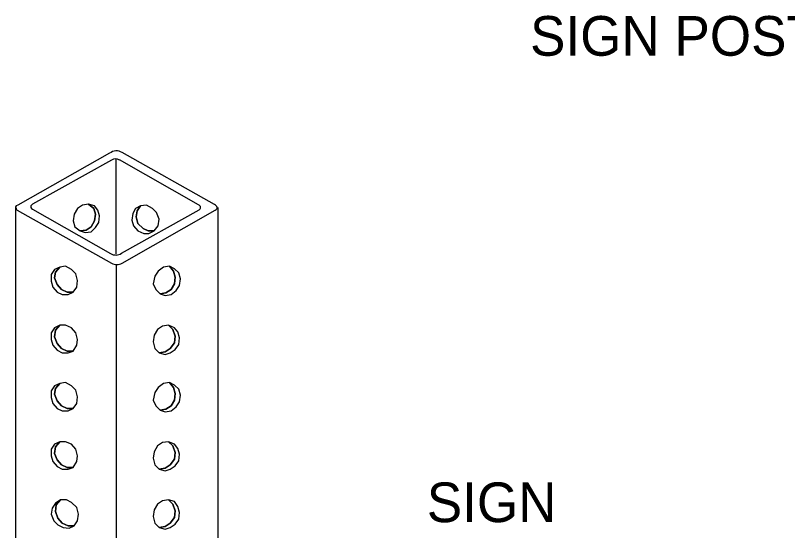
# Model space of a CAD drawing. Extents: x 99862 to 103680, y 99470 to 102076.
# Drawn here: x 100406.5 to 100717.9, y 100290.3 to 100498 of the extents above; entities that cross this region are included whole.
import ezdxf

# ---------------------------------------------------------------- set-up
doc = ezdxf.new("R2010")
doc.units = 0
doc.layers.add('Level 2', color=7, linetype='Continuous')
doc.layers.add('Level 20', color=7, linetype='Continuous')

msp = doc.modelspace()

# ---------------------------------------------------------------- linework, layer by layer
at = {"layer": 'Level 2'}
for p, q in [((100444.49, 100442.41), (100407.52, 100421.53)), ((100486.78, 100421.72), (100449.53, 100442.7)), ((100445.25, 100439.63), (100413.35, 100421.87)), ((100446.97, 100439.97), (100446.97, 100401.75)), ((100480.33, 100421.68), (100448.41, 100439.77)), ((100406.83, 100421.2), (100406.49, 100420.86)), ((100406.49, 100420.86), (100406.49, 100420.53)), ((100406.49, 100420.53), (100406.83, 100420.19)), ((100406.49, 100420.53), (100406.49, 100093.86)), ((100407.52, 100421.53), (100406.83, 100421.2)), ((100413.01, 100421.53), (100412.66, 100421.2)), ((100412.66, 100421.2), (100412.66, 100420.86)), ((100412.66, 100420.86), (100412.66, 100420.53)), ((100412.66, 100420.53), (100413.01, 100420.19)), ((100413.35, 100421.87), (100413.01, 100421.53)), ((100433.59, 100421.53), (100431.53, 100420.19)), ((100435.99, 100421.87), (100433.59, 100421.53)), ((100438.05, 100420.19), (100435.99, 100421.87)), ((100438.39, 100421.2), (100435.99, 100421.87)), ((100435.99, 100421.87), (100438.05, 100420.19)), ((100439.77, 100419.52), (100438.39, 100421.2)), ((100456.92, 100421.2), (100454.86, 100420.19)), ((100456.92, 100421.2), (100455.55, 100419.18)), ((100455.55, 100419.18), (100456.92, 100421.2)), ((100459.32, 100421.53), (100456.92, 100421.2)), ((100461.72, 100420.19), (100459.32, 100421.53)), ((100488.14, 100420.6), (100488.14, 100093.86)), ((100406.83, 100420.19), (100406.83, 100419.86)), ((100406.83, 100419.86), (100407.18, 100419.52)), ((100407.18, 100419.52), (100445.25, 100398.07)), ((100413.01, 100420.19), (100413.35, 100419.86)), ((100413.35, 100419.86), (100444.88, 100401.97)), ((100430.16, 100417.84), (100429.82, 100415.16)), ((100431.53, 100420.19), (100430.16, 100417.84)), ((100438.74, 100417.84), (100438.05, 100420.19)), ((100438.05, 100420.19), (100438.74, 100417.84)), ((100438.39, 100415.16), (100438.74, 100417.84)), ((100438.74, 100417.84), (100438.39, 100415.16)), ((100440.45, 100417.17), (100439.77, 100419.52)), ((100449.31, 100402.1), (100480.55, 100419.64)), ((100449.57, 100398.18), (100487.11, 100419.52)), ((100453.83, 100418.18), (100453.49, 100415.5)), ((100454.86, 100420.19), (100453.83, 100418.18)), ((100455.55, 100419.18), (100455.2, 100416.84)), ((100455.2, 100416.84), (100455.55, 100419.18)), ((100463.44, 100418.51), (100461.72, 100420.19)), ((100464.47, 100415.83), (100463.44, 100418.51)), ((100487.11, 100419.52), (100487.11, 100419.52)), ((100429.82, 100415.16), (100430.5, 100412.82)), ((100437.02, 100412.82), (100438.39, 100415.16)), ((100438.39, 100415.16), (100437.02, 100412.82)), ((100438.74, 100412.48), (100440.11, 100414.49)), ((100440.11, 100414.49), (100440.45, 100417.17)), ((100453.49, 100415.5), (100454.17, 100413.15)), ((100455.2, 100416.84), (100455.89, 100414.16)), ((100455.89, 100414.16), (100455.2, 100416.84)), ((100464.12, 100413.15), (100464.47, 100415.83)), ((100430.5, 100412.82), (100432.56, 100411.14)), ((100432.56, 100411.14), (100434.96, 100411.47)), ((100434.96, 100411.47), (100432.56, 100411.14)), ((100434.96, 100411.47), (100437.02, 100412.82)), ((100437.02, 100412.82), (100434.96, 100411.47)), ((100437.02, 100410.8), (100438.74, 100412.48)), ((100454.17, 100413.15), (100455.89, 100411.14)), ((100455.89, 100414.16), (100457.95, 100412.15)), ((100457.95, 100412.15), (100455.89, 100414.16)), ((100457.95, 100412.15), (100460.01, 100411.14)), ((100460.01, 100411.14), (100457.95, 100412.15)), ((100462.41, 100411.14), (100464.12, 100413.15)), ((100432.56, 100411.14), (100434.62, 100410.47)), ((100434.62, 100410.47), (100437.02, 100410.8)), ((100455.89, 100411.14), (100458.29, 100410.13)), ((100458.29, 100410.13), (100460.35, 100410.13)), ((100460.01, 100411.14), (100462.41, 100411.14)), ((100462.41, 100411.14), (100460.01, 100411.14)), ((100460.35, 100410.13), (100462.41, 100411.14)), ((100424.33, 100396.56), (100422.27, 100395.55)), ((100424.33, 100396.56), (100422.61, 100394.55)), ((100422.61, 100394.55), (100424.33, 100396.56)), ((100426.73, 100396.89), (100424.33, 100396.56)), ((100429.13, 100395.55), (100426.73, 100396.89)), ((100447.31, 100071.74), (100447.31, 100397.53)), ((100466.18, 100396.56), (100464.12, 100394.88)), ((100468.58, 100396.89), (100466.18, 100396.56)), ((100470.3, 100394.88), (100468.58, 100396.89)), ((100470.64, 100395.89), (100468.58, 100396.89)), ((100468.58, 100396.89), (100470.3, 100394.88)), ((100472.36, 100394.21), (100470.64, 100395.89)), ((100422.27, 100395.55), (100420.9, 100393.54)), ((100420.9, 100393.54), (100420.9, 100390.86)), ((100422.61, 100394.55), (100422.27, 100392.2)), ((100422.27, 100392.2), (100422.61, 100394.55)), ((100430.85, 100393.88), (100429.13, 100395.55)), ((100431.53, 100391.19), (100430.85, 100393.88)), ((100462.75, 100392.87), (100462.06, 100389.85)), ((100464.12, 100394.88), (100462.75, 100392.87)), ((100470.98, 100392.54), (100470.3, 100394.88)), ((100470.3, 100394.88), (100470.98, 100392.54)), ((100470.64, 100389.85), (100470.98, 100392.54)), ((100470.98, 100392.54), (100470.64, 100389.85)), ((100473.04, 100391.86), (100472.36, 100394.21)), ((100420.9, 100390.86), (100421.58, 100388.51)), ((100422.27, 100392.2), (100423.3, 100389.52)), ((100423.3, 100389.52), (100422.27, 100392.2)), ((100423.3, 100389.52), (100425.01, 100387.51)), ((100425.01, 100387.51), (100423.3, 100389.52)), ((100431.19, 100388.51), (100431.53, 100391.19)), ((100462.06, 100389.85), (100463.09, 100387.51)), ((100469.27, 100387.51), (100470.64, 100389.85)), ((100470.64, 100389.85), (100469.27, 100387.51)), ((100472.7, 100389.18), (100473.04, 100391.86)), ((100421.58, 100388.51), (100423.3, 100386.5)), ((100423.3, 100386.5), (100425.36, 100385.5)), ((100425.01, 100387.51), (100427.42, 100386.5)), ((100427.42, 100386.5), (100425.01, 100387.51)), ((100427.42, 100386.5), (100429.82, 100386.5)), ((100429.82, 100386.5), (100427.42, 100386.5)), ((100427.76, 100385.5), (100429.82, 100386.5)), ((100429.82, 100386.5), (100431.19, 100388.51)), ((100463.09, 100387.51), (100464.81, 100385.83)), ((100467.21, 100386.17), (100469.27, 100387.51)), ((100469.27, 100387.51), (100467.21, 100386.17)), ((100469.27, 100385.5), (100471.33, 100387.17)), ((100471.33, 100387.17), (100472.7, 100389.18)), ((100425.36, 100385.5), (100427.76, 100385.5)), ((100464.81, 100385.83), (100467.21, 100386.17)), ((100467.21, 100386.17), (100464.81, 100385.83)), ((100464.81, 100385.83), (100466.87, 100385.16)), ((100466.87, 100385.16), (100469.27, 100385.5)), ((100422.27, 100372.09), (100420.9, 100370.08)), ((100424.33, 100373.09), (100422.27, 100372.09)), ((100422.61, 100371.08), (100422.27, 100368.4)), ((100422.27, 100368.4), (100422.61, 100371.08)), ((100424.33, 100373.09), (100422.61, 100371.08)), ((100422.61, 100371.08), (100424.33, 100373.09)), ((100426.73, 100373.09), (100424.33, 100373.09)), ((100429.13, 100372.09), (100426.73, 100373.09)), ((100430.85, 100370.08), (100429.13, 100372.09)), ((100463.78, 100371.42), (100462.41, 100369.07)), ((100465.84, 100372.76), (100463.78, 100371.42)), ((100468.24, 100373.09), (100465.84, 100372.76)), ((100469.95, 100371.42), (100468.24, 100373.09)), ((100470.64, 100372.09), (100468.24, 100373.09)), ((100468.24, 100373.09), (100469.95, 100371.42)), ((100470.98, 100368.73), (100469.95, 100371.42)), ((100469.95, 100371.42), (100470.98, 100368.73)), ((100472.01, 100370.41), (100470.64, 100372.09)), ((100420.9, 100370.08), (100420.9, 100367.39)), ((100422.27, 100368.4), (100423.3, 100365.72)), ((100423.3, 100365.72), (100422.27, 100368.4)), ((100431.53, 100367.39), (100430.85, 100370.08)), ((100462.41, 100369.07), (100462.06, 100366.39)), ((100470.64, 100366.05), (100470.98, 100368.73)), ((100470.98, 100368.73), (100470.64, 100366.05)), ((100472.7, 100368.06), (100472.01, 100370.41)), ((100472.36, 100365.38), (100472.7, 100368.06)), ((100420.9, 100367.39), (100421.58, 100365.05)), ((100421.58, 100365.05), (100423.3, 100363.04)), ((100423.3, 100365.72), (100425.01, 100363.71)), ((100425.01, 100363.71), (100423.3, 100365.72)), ((100429.82, 100362.7), (100431.19, 100365.05)), ((100431.19, 100365.05), (100431.53, 100367.39)), ((100462.06, 100366.39), (100462.75, 100363.71)), ((100468.93, 100363.71), (100470.64, 100366.05)), ((100470.64, 100366.05), (100468.93, 100363.71)), ((100470.98, 100363.37), (100472.36, 100365.38)), ((100423.3, 100363.04), (100425.36, 100362.03)), ((100425.01, 100363.71), (100427.42, 100362.7)), ((100427.42, 100362.7), (100425.01, 100363.71)), ((100425.36, 100362.03), (100427.76, 100362.03)), ((100427.42, 100362.7), (100429.82, 100362.7)), ((100429.82, 100362.7), (100427.42, 100362.7)), ((100427.76, 100362.03), (100429.82, 100362.7)), ((100462.75, 100363.71), (100464.47, 100362.03)), ((100464.47, 100362.03), (100466.87, 100362.37)), ((100466.87, 100362.37), (100464.47, 100362.03)), ((100464.47, 100362.03), (100466.87, 100361.36)), ((100466.87, 100362.37), (100468.93, 100363.71)), ((100468.93, 100363.71), (100466.87, 100362.37)), ((100466.87, 100361.36), (100468.93, 100362.03)), ((100468.93, 100362.03), (100470.98, 100363.37)), ((100424.33, 100349.63), (100422.27, 100348.62)), ((100424.33, 100349.63), (100422.61, 100347.62)), ((100422.61, 100347.62), (100424.33, 100349.63)), ((100426.73, 100349.96), (100424.33, 100349.63)), ((100429.13, 100348.62), (100426.73, 100349.96)), ((100466.18, 100349.63), (100464.12, 100347.95)), ((100468.58, 100349.96), (100466.18, 100349.63)), ((100470.3, 100347.95), (100468.58, 100349.96)), ((100470.64, 100348.96), (100468.58, 100349.96)), ((100468.58, 100349.96), (100470.3, 100347.95)), ((100472.36, 100347.28), (100470.64, 100348.96)), ((100422.27, 100348.62), (100420.9, 100346.61)), ((100420.9, 100346.61), (100420.9, 100343.93)), ((100422.61, 100347.62), (100422.27, 100345.27)), ((100422.27, 100345.27), (100422.61, 100347.62)), ((100430.85, 100346.95), (100429.13, 100348.62)), ((100431.53, 100344.26), (100430.85, 100346.95)), ((100462.75, 100345.94), (100462.06, 100342.92)), ((100464.12, 100347.95), (100462.75, 100345.94)), ((100470.98, 100345.61), (100470.3, 100347.95)), ((100470.3, 100347.95), (100470.98, 100345.61)), ((100473.04, 100344.93), (100472.36, 100347.28)), ((100420.9, 100343.93), (100421.58, 100341.58)), ((100422.27, 100345.27), (100423.3, 100342.59)), ((100423.3, 100342.59), (100422.27, 100345.27)), ((100431.19, 100341.58), (100431.53, 100344.26)), ((100462.06, 100342.92), (100463.09, 100340.58)), ((100469.27, 100340.58), (100470.64, 100342.92)), ((100470.64, 100342.92), (100469.27, 100340.58)), ((100470.64, 100342.92), (100470.98, 100345.61)), ((100470.98, 100345.61), (100470.64, 100342.92)), ((100472.7, 100342.25), (100473.04, 100344.93)), ((100421.58, 100341.58), (100423.3, 100339.57)), ((100423.3, 100342.59), (100425.01, 100340.58)), ((100425.01, 100340.58), (100423.3, 100342.59)), ((100423.3, 100339.57), (100425.36, 100338.57)), ((100425.01, 100340.58), (100427.42, 100339.57)), ((100427.42, 100339.57), (100425.01, 100340.58)), ((100427.42, 100339.57), (100429.82, 100339.57)), ((100429.82, 100339.57), (100427.42, 100339.57)), ((100427.76, 100338.57), (100429.82, 100339.57)), ((100429.82, 100339.57), (100431.19, 100341.58)), ((100463.09, 100340.58), (100464.81, 100338.9)), ((100467.21, 100339.24), (100469.27, 100340.58)), ((100469.27, 100340.58), (100467.21, 100339.24)), ((100469.27, 100338.57), (100471.33, 100340.24)), ((100471.33, 100340.24), (100472.7, 100342.25)), ((100425.36, 100338.57), (100427.76, 100338.57)), ((100464.81, 100338.9), (100467.21, 100339.24)), ((100467.21, 100339.24), (100464.81, 100338.9)), ((100464.81, 100338.9), (100466.87, 100338.23)), ((100466.87, 100338.23), (100469.27, 100338.57)), ((100422.27, 100325.16), (100420.9, 100323.15)), ((100424.33, 100326.16), (100422.27, 100325.16)), ((100422.61, 100324.15), (100422.27, 100321.47)), ((100422.27, 100321.47), (100422.61, 100324.15)), ((100424.33, 100326.16), (100422.61, 100324.15)), ((100422.61, 100324.15), (100424.33, 100326.16)), ((100426.73, 100326.16), (100424.33, 100326.16)), ((100429.13, 100325.16), (100426.73, 100326.16)), ((100430.85, 100323.15), (100429.13, 100325.16)), ((100463.78, 100324.49), (100462.41, 100322.14)), ((100465.84, 100325.83), (100463.78, 100324.49)), ((100468.24, 100326.16), (100465.84, 100325.83)), ((100469.95, 100324.49), (100468.24, 100326.16)), ((100470.64, 100325.16), (100468.24, 100326.16)), ((100468.24, 100326.16), (100469.95, 100324.49)), ((100470.98, 100321.8), (100469.95, 100324.49)), ((100469.95, 100324.49), (100470.98, 100321.8)), ((100472.01, 100323.48), (100470.64, 100325.16)), ((100420.9, 100323.15), (100420.9, 100320.46)), ((100422.27, 100321.47), (100423.3, 100318.79)), ((100423.3, 100318.79), (100422.27, 100321.47)), ((100431.53, 100320.46), (100430.85, 100323.15)), ((100462.41, 100322.14), (100462.06, 100319.46)), ((100470.64, 100319.12), (100470.98, 100321.8)), ((100470.98, 100321.8), (100470.64, 100319.12)), ((100472.7, 100321.13), (100472.01, 100323.48)), ((100472.36, 100318.45), (100472.7, 100321.13)), ((100420.9, 100320.46), (100421.58, 100318.12)), ((100421.58, 100318.12), (100423.3, 100316.11)), ((100423.3, 100318.79), (100425.01, 100316.78)), ((100425.01, 100316.78), (100423.3, 100318.79)), ((100429.82, 100315.77), (100431.19, 100318.12)), ((100431.19, 100318.12), (100431.53, 100320.46)), ((100462.06, 100319.46), (100462.75, 100316.78)), ((100468.93, 100316.78), (100470.64, 100319.12)), ((100470.64, 100319.12), (100468.93, 100316.78)), ((100470.98, 100316.44), (100472.36, 100318.45)), ((100423.3, 100316.11), (100425.36, 100315.1)), ((100425.01, 100316.78), (100427.42, 100315.77)), ((100427.42, 100315.77), (100425.01, 100316.78)), ((100425.36, 100315.1), (100427.76, 100315.1)), ((100427.42, 100315.77), (100429.82, 100315.77)), ((100429.82, 100315.77), (100427.42, 100315.77)), ((100427.76, 100315.1), (100429.82, 100315.77)), ((100462.75, 100316.78), (100464.47, 100315.1)), ((100464.47, 100315.1), (100466.87, 100315.44)), ((100466.87, 100315.44), (100464.47, 100315.1)), ((100464.47, 100315.1), (100466.87, 100314.43)), ((100466.87, 100315.44), (100468.93, 100316.78)), ((100468.93, 100316.78), (100466.87, 100315.44)), ((100466.87, 100314.43), (100468.93, 100315.1)), ((100468.93, 100315.1), (100470.98, 100316.44)), ((100424.67, 100302.7), (100422.61, 100301.36)), ((100424.67, 100302.7), (100422.96, 100300.69)), ((100422.96, 100300.69), (100424.67, 100302.7)), ((100427.07, 100302.7), (100424.67, 100302.7)), ((100429.13, 100301.69), (100427.07, 100302.7)), ((100465.84, 100302.36), (100463.78, 100301.02)), ((100468.24, 100302.7), (100465.84, 100302.36)), ((100469.95, 100301.02), (100468.24, 100302.7)), ((100470.64, 100302.03), (100468.24, 100302.7)), ((100468.24, 100302.7), (100469.95, 100301.02)), ((100421.24, 100299.35), (100420.9, 100297)), ((100422.61, 100301.36), (100421.24, 100299.35)), ((100422.96, 100300.69), (100422.61, 100298)), ((100422.61, 100298), (100422.96, 100300.69)), ((100431.19, 100299.68), (100429.13, 100301.69)), ((100431.88, 100297), (100431.19, 100299.68)), ((100463.78, 100301.02), (100462.41, 100298.68)), ((100470.98, 100298.34), (100469.95, 100301.02)), ((100469.95, 100301.02), (100470.98, 100298.34)), ((100472.01, 100300.02), (100470.64, 100302.03)), ((100472.7, 100297.67), (100472.01, 100300.02)), ((100420.9, 100297), (100421.93, 100294.32)), ((100422.61, 100298), (100423.64, 100295.32)), ((100423.64, 100295.32), (100422.61, 100298)), ((100431.53, 100294.32), (100431.88, 100297)), ((100462.41, 100298.68), (100462.06, 100295.99)), ((100462.06, 100295.99), (100462.75, 100293.31)), ((100470.64, 100295.66), (100470.98, 100298.34)), ((100470.98, 100298.34), (100470.64, 100295.66)), ((100472.36, 100294.99), (100472.7, 100297.67)), ((100421.93, 100294.32), (100423.64, 100292.64)), ((100423.64, 100295.32), (100425.36, 100293.31)), ((100425.36, 100293.31), (100423.64, 100295.32)), ((100425.36, 100293.31), (100427.76, 100292.31)), ((100427.76, 100292.31), (100425.36, 100293.31)), ((100430.16, 100292.31), (100431.53, 100294.32)), ((100462.75, 100293.31), (100464.47, 100291.64)), ((100466.87, 100291.97), (100468.93, 100293.31)), ((100468.93, 100293.31), (100466.87, 100291.97)), ((100468.93, 100293.31), (100470.64, 100295.66)), ((100470.64, 100295.66), (100468.93, 100293.31)), ((100468.93, 100291.64), (100470.98, 100292.98)), ((100470.98, 100292.98), (100472.36, 100294.99)), ((100423.64, 100292.64), (100425.7, 100291.64)), ((100425.7, 100291.64), (100428.1, 100291.3)), ((100427.76, 100292.31), (100430.16, 100292.31)), ((100430.16, 100292.31), (100427.76, 100292.31)), ((100428.1, 100291.3), (100430.16, 100292.31)), ((100464.47, 100291.64), (100466.87, 100291.97)), ((100466.87, 100291.97), (100464.47, 100291.64)), ((100464.47, 100291.64), (100466.87, 100290.97)), ((100466.87, 100290.97), (100468.93, 100291.64))]:
    msp.add_line(p, q, dxfattribs=at)
for centre, radius, start, end in [((100447.21, 100439.01), 4.36, 57.8456, 128.7047), ((100446.94, 100437.03), 3.11, 59.5352, 123.7544)]:
    msp.add_arc(centre, radius, start, end, dxfattribs=at)
for centre, major_axis, ratio, start_param, end_param in [((100478.91, 100420.72), (2.26, -0.28), 0.602426, 5.596826, 7.251173), ((100485.57, 100420.65), (2.26, -0.28), 0.602426, 5.534239, 7.365304), ((100446.98, 100405.15), (4.03, -0.01), 0.92641, 4.165986, 5.330706), ((100447.31, 100401.26), (4.03, -0.01), 0.923602, 4.165986, 5.311309)]:
    msp.add_ellipse(centre, major_axis=major_axis, ratio=ratio, start_param=start_param, end_param=end_param, dxfattribs=at)

# ---------------------------------------------------------------- texts
at = {"layer": 'Level 20'}
msp.add_text('SIGN POST', height=16, dxfattribs=at).set_placement((100614.08, 100481.75))
msp.add_text('SIGN', height=16, rotation=360, dxfattribs=at).set_placement((100572.43, 100293.73))

doc.saveas('drawing.dxf')
